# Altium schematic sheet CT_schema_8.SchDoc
size 274 x 160 mm
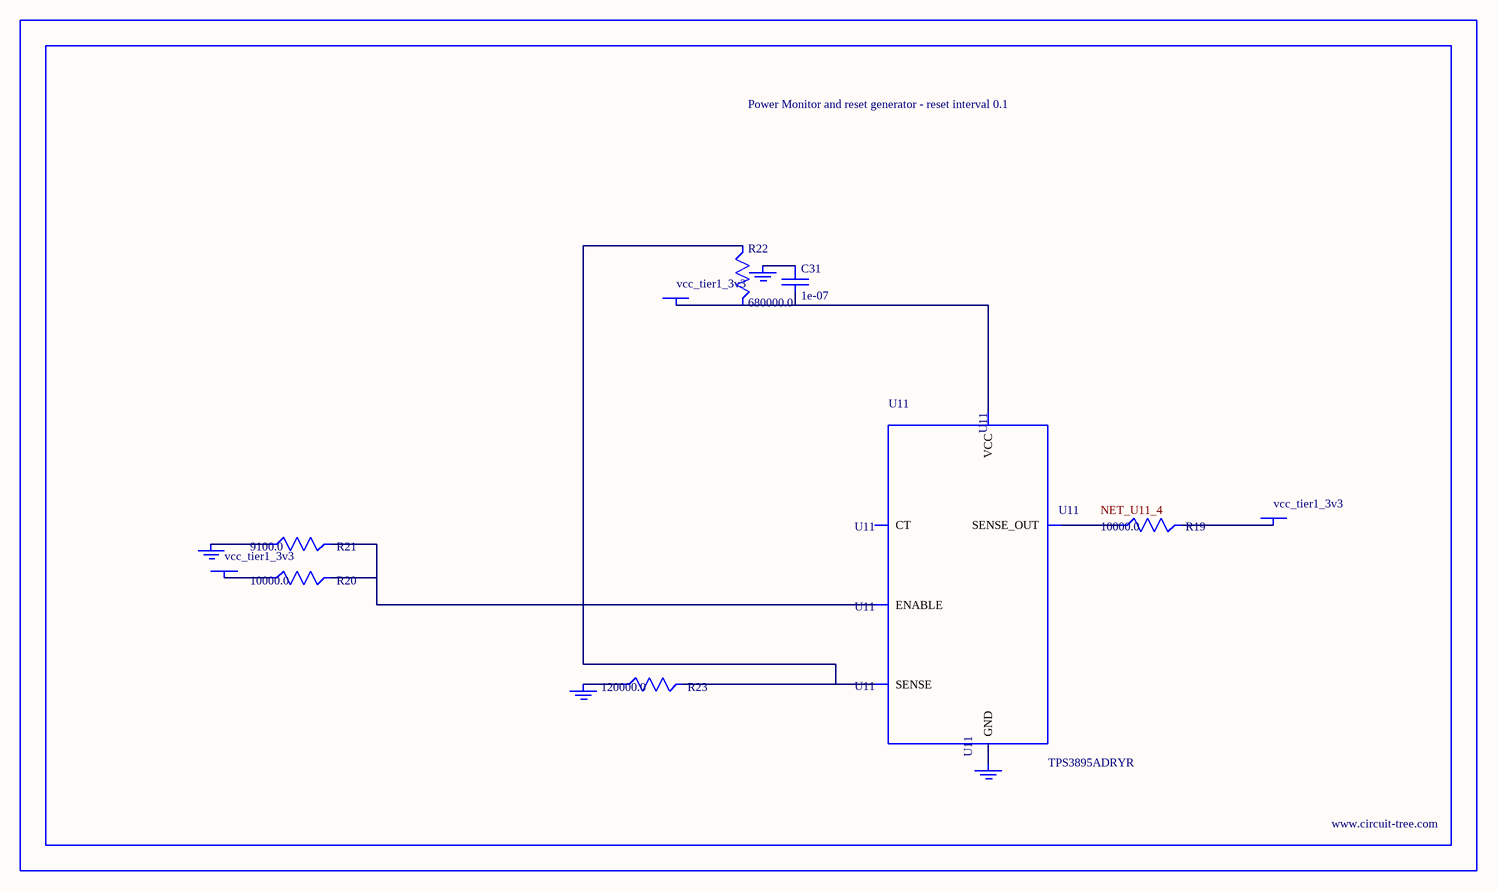
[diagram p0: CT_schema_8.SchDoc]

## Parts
BORDER7  (no value)
C31  1e-07  [C0402]
GND_INSTANCE_7_0  (no value)
GND_INSTANCE_7_1  (no value)
GND_INSTANCE_7_2  (no value)
GND_INSTANCE_7_3  (no value)
POWER_INSTANCE_7_0  vcc_tier1_3v3
POWER_INSTANCE_7_1  vcc_tier1_3v3
POWER_INSTANCE_7_2  vcc_tier1_3v3
R19  10000.0  [R0603]
R20  10000.0  [R0603]
R21  9100.0  [R0603]
R22  680000.0  [R0603]
R23  120000.0  [R0603]
U11  TPS3895ADRYR  [SON-6]

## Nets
NetC31_1: C31.1 GND_INSTANCE_7_2.0(GND)
NetC31_2: C31.2 POWER_INSTANCE_7_2.0(PWR) R22.2 U11.6(VCC)
NetGND_INSTANCE_7_0_0: GND_INSTANCE_7_0.0(GND) R21.1
NetGND_INSTANCE_7_1_0: GND_INSTANCE_7_1.0(GND) R23.1
NetGND_INSTANCE_7_3_0: GND_INSTANCE_7_3.0(GND) U11.2(GND)
NetPOWER_INSTANCE_7_0_0: POWER_INSTANCE_7_0.0(PWR) R20.1
NetPOWER_INSTANCE_7_1_0: POWER_INSTANCE_7_1.0(PWR) R19.2
NetR19_1: R19.1 U11.4(SENSE_OUT)
NetR20_2: R20.2 R21.2 U11.1(ENABLE)
NetR22_1: R22.1 R23.2 U11.3(SENSE)

Not connected (* = marked no-connect by the designer): U11 5(CT)

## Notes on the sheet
- Labels drawn without touching a wire or pin: NET_U11_4

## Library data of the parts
BORDER7 = BORDER_PAGE7
C31 = C0402C104K3RACTU
GND_INSTANCE_7_0-GND_INSTANCE_7_3 = GND
POWER_INSTANCE_7_0-POWER_INSTANCE_7_2 = PWR
R19 R20 = RC0603JR-0710KL
R21 = RC0603JR-079K1L
R22 = RC0603JR-07680KL
R23 = RC0603JR-07120KL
